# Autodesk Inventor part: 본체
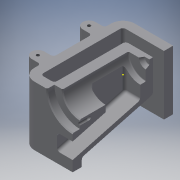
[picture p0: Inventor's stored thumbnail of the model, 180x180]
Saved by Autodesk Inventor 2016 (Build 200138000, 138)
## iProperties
Created: 2022-03
Part Number: 본체
Material: 일반
Document SubType Name: Modeling
Designer: CAD01
Density: 1 g/cm^3
Appearance: 기본값
Author: CAD01
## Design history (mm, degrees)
sketch "스케치1"
  geometry: L1 (-55, -55)-(55, -55); L2 (55, -55)-(55, 55); L3 (55, 55)-(-55, 55); L4 (-55, 55)-(-55, -55); L5 (-55, -55)-(55, 55); L6 (55, -55)-(-55, 55); 1 further point
  constraints: 12 end point, 2 midpoint, 2 parallel, 1 horizontal, 1 perpendicular
  dimensions: "d0" = 110 distance of L3.end L2.end; "d1" = 110 distance of L2.end L1.end
extrude "돌출1" new body sketch "스케치1" distance "d2" = 65; taper "d3" = 0 deg
sketch "스케치2"
  geometry: L1 (-55, 65)-(-55, 37); L2 (-55, 0)-(-55, 65) reference; L3 (-47, 37)-(-47, 65); L4 (-55, 37)-(-47, 37); L5 (-55, 65)-(55, 65) reference; L6 (55, 65)-(-55, 65); L7 (-47, 46)-(25, 46); L8 (25, 46)-(25, 65); 1 further point
  constraints: 12 end point, 4 point on line, 2 horizontal, 1 perpendicular, 1 vertical
  dimensions: "d4" = 8 distance of L1.end L3.start; "d5" = 28 distance of L1.start L1.end; "d6" = 72 distance of L7.start L7.end; "d8" = 19 distance between parallel lines of L7 L5
revolve "회전1" sketch "스케치2" stored, may be unused: angle "d10" = 90 deg
sketch "스케치3"
  geometry: L1 (-30, 45)-(-30, -45); L2 (-55, 55)-(-55, -55) reference; L3 (-45, -45)-(-45, 45); L4 (-45, 45)-(45, 45); L5 (55, 55)-(-55, 55) reference; L6 (45, 45)-(45, -45); L7 (55, -55)-(55, 55) reference; L8 (30, 45)-(30, -45); L9 (-45, 33)-(45, 33); L10 (-45, -45)-(45, -45); L11 (28, -55)-(55, -55) reference; 1 further point
  constraints: 14 end point, 6 point on line, 4 vertical, 3 horizontal
  dimensions: "d11" = 25 distance between parallel lines of L2 L1; "d12" = 10 distance between parallel lines of L2 L3; "d13" = 10 distance between parallel lines of L5 L4; "d14" = 10 distance between parallel lines of L7 L6; "d15" = 25 distance between parallel lines of L7 L8; "d16" = 22 distance between parallel lines of L5 L9; "d17" = 10 distance between parallel lines of L11 L10
extrude "돌출2" cut sketch "스케치3" stored distance "d18" = 65; taper "d19" = 0 deg
sketch "스케치4"
  geometry: L1 (33, 0)-(33, 65) reference; L2 (33, 0)-(33, 30); L3 (33, 30)-(-45, 9.1); L4 (19, 31.425)-(-55, 11.597); L5 (-19, 38.843)-(-55, 29.197); L6 (19, 65)-(-19, 65); L7 (-55, 37)-(-55, 65) reference; L8 (19, 65)-(19, 31.425); L9 (-19, 65)-(-19, 38.843); L10 (-55, 0)-(-55, 65) reference; L11 (-55, 11.597)-(-55, 29.197); L12 (-47, 37)-(-47, 65) reference; L13 (55, 0)-(55, 65) reference; L14 (-45, 0)-(33, 0) reference; L15 (-45, 0)-(-45, 9.1) reference; L16 (-47, 65)-(25, 65); L17 (-45, 65)-(45, 65) reference; 2 further points
  constraints: 22 end point, 6 point on line, 3 horizontal, 3 parallel, 2 midpoint, 2 vertical
  dimensions: "d20" = 30 distance of L1.start L2.end; "d21" = 75 deg angle of L1 L3; "d22" = 5 distance between parallel lines of L3 L4; "d23" = 17 distance between parallel lines of L4 L5; "d24" = 38 distance of L6.start L6.end; "d25" = 36 distance from line of L7 L6.end
extrude "돌출3" cut sketch "스케치4" stored distance "d26" = 34; taper "d27" = 0 deg
sketch "스케치5"
  geometry: L1 (55, 55)-(-55, 55) reference; L2 (0, 77)-(0, -77) reference; L3 (-55, 55)-(-55, -55); L4 (-65, 28)-(-65, 21); L5 (-65, 21)-(-55, 21); L6 (-65, 28)-(-65, 35); L7 (-65, 35)-(-55, 35); A1 r 7 centre (-65, 28) between (-65, 21) and (-65, 35); 1 further point
  constraints: 10 end point, 3 vertical, 2 horizontal, 2 point on circle, 2 point on line, 1 centre point
  dimensions: "d28" = 14 diameter of A1; "d29" = 27 distance from line of L1 L4.start; "d30" = 65 distance from line of L4.start L2
extrude "돌출4" join sketch "스케치5" distance "d31" = 20; taper "d32" = 0 deg
sketch "스케치6"
  geometry: C1 r 1 at (65, -28); A1 r 7 centre (65, -28) between (65, -35) and (65, -21) reference; 1 further point
  constraints: 1 centre point, 1 concentric
  dimensions: "d36" = 2 diameter of C1
hole "구멍1" sketch "스케치6" at (65, -28) diameter "d37" = 3.459; stored, may be unused: countersink angle "d41" = 90 deg, drill point angle "d43" = 118 deg; dims "d38" = 9, "d39" = 4, "d40" = 2, "d42" = 11
sketch "스케치7"
  geometry: L1 (0, 77)-(0, -77) reference; L2 (-19, 25)-(19, 25) reference; L3 (-7.5, 25)-(-5.191, 29); L4 (7.5, 25)-(5.191, 29); L5 (-5.191, 29)-(5.191, 29); L6 (-7.5, 25)-(7.5, 25); L7 (0, 29)-(0, 25); 1 further point
  constraints: 10 end point, 3 point on line, 2 midpoint, 1 collinear, 1 horizontal
  dimensions: "d52" = 30 deg angle of L1 L4; "d53" = 60 deg angle of L4 L3; "d55" = 4 distance between parallel lines of L2 L5; "d56" = 15 distance of L4.start L3.start; "d57" = 7.5 distance from line of L1 L3.start
revolve "회전2" sketch "스케치7" stored, may be unused: angle "d58" = 90 deg
extrude "돌출5" cut sketch "스케치4" stored distance "d59" = 20; taper "d60" = 0 deg
extrude "돌출6" cut sketch "스케치4" stored distance "d61" = 20; taper "d62" = 0 deg
sketch "스케치8" dims "d66" = 46
  geometry: L1 (30, 0)-(-30, 0) reference; L2 (0, -23)-(0, 0); 1 further point
  constraints: 2 end point, 1 midpoint, 1 vertical, 1 vertical alignment, 2 other
hole "구멍2" sketch "스케치8" at (0, -23) diameter "d67" = 3.459; stored, may be unused: countersink angle "d71" = 90 deg, drill point angle "d73" = 118 deg; dims "d68" = 9, "d69" = 4, "d70" = 2, "d72" = 11
fillet "모깎기1" dims "d74" = 3
fillet "모깎기2" dims "d75" = 3
fillet "모깎기3" dims "d76" = 3
fillet "모깎기4" dims "d77" = 3
sketch "스케치9"
  geometry: 1 further point
fillet "모깎기5" dims "d78" = 3
fillet "모깎기6" dims "d79" = 3
fillet "모깎기7" dims "d80" = 3
fillet "모깎기8" dims "d81" = 3
sketch "스케치10"
  geometry: L1 (0, 0)-(-65, 0) reference; L2 (0, 0)-(0, 110) reference; 2 further points
  constraints: 1 other
  dimensions: "d82" = 55 distance from line of L1 point (-20, 55); "d83" = 20 distance from line of L2 point (-20, 55)
feature "엠보싱1" sketch "스케치10" dims "d84" = 0.5, "d85" = 0
fillet "모깎기9" dims "d86" = 13
fillet "모깎기10" dims "d87" = 3
fillet "모깎기11" dims "d88" = 1
chamfer "모따기2" distance "d89" = 1; stored, may be unused: second distance "d90" = 2, angle "d91" = 45 deg
feature "분할1"
node "솔리드1"
pattern_linear "직사각형 패턴1" dims "d35" = 56
mirror "대칭1"
pattern_linear "직사각형 패턴2" dims "d46" = 56
